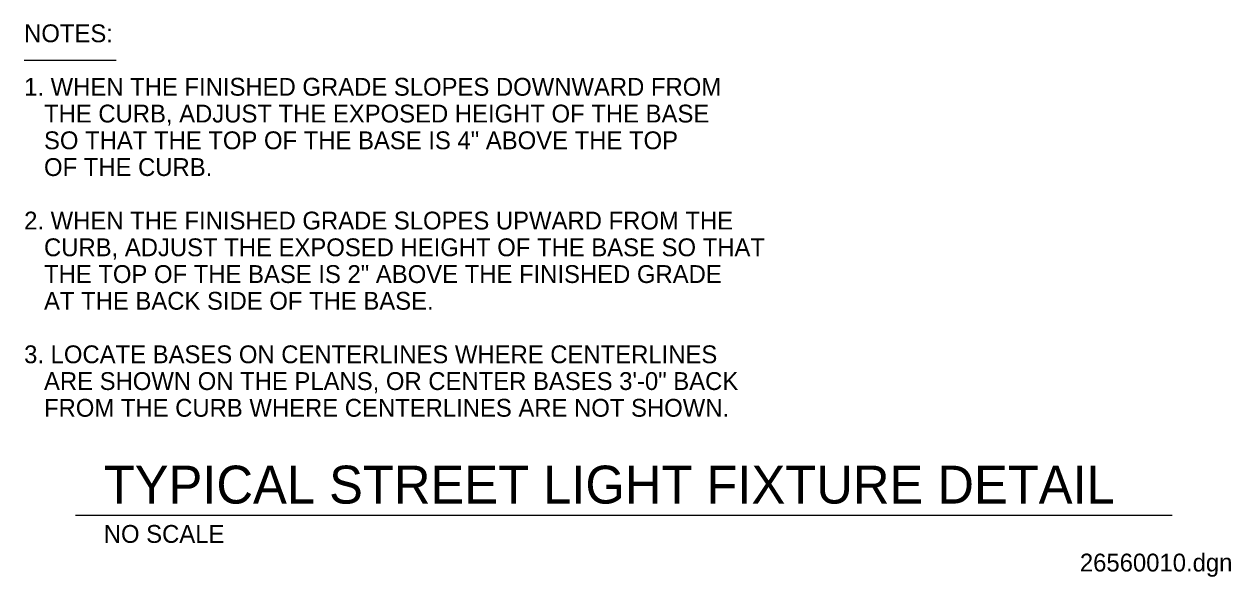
# Model space of a CAD drawing. Extents: x 10112 to 10168, y 10050 to 10179.
# Drawn here: x 10119.91 to 10165.01, y 10050.13 to 10070.8 of the extents above; entities that cross this region are included whole.
import ezdxf

# ---------------------------------------------------------------- set-up
doc = ezdxf.new("R2010")
doc.units = 0
doc.layers.add('G-ANNO-TEXT', color=7, linetype='Continuous')

msp = doc.modelspace()

# ---------------------------------------------------------------- linework, layer by layer
at = {"layer": 'G-ANNO-TEXT'}
for p, q in [((10119.906, 10069.453), (10123.34, 10069.453)), ((10121.82, 10052.441), (10162.811, 10052.441))]:
    msp.add_line(p, q, dxfattribs=at)

# ---------------------------------------------------------------- texts
for s, height, p in [('NOTES:', 0.6667, (10119.906, 10070.12)), ('1. WHEN THE FINISHED GRADE SLOPES DOWNWARD FROM', 0.66667, (10119.906, 10068.12)), ('   THE CURB, ADJUST THE EXPOSED HEIGHT OF THE BASE ', 0.66667, (10119.906, 10067.12)), ('   SO THAT THE TOP OF THE BASE IS 4" ABOVE THE TOP ', 0.66667, (10119.906, 10066.12)), ('   OF THE CURB.', 0.66667, (10119.906, 10065.12)), ('2. WHEN THE FINISHED GRADE SLOPES UPWARD FROM THE ', 0.66667, (10119.906, 10063.12)), ('   CURB, ADJUST THE EXPOSED HEIGHT OF THE BASE SO THAT ', 0.66667, (10119.906, 10062.12)), ('   THE TOP OF THE BASE IS 2" ABOVE THE FINISHED GRADE ', 0.66667, (10119.906, 10061.12)), ('   AT THE BACK SIDE OF THE BASE.', 0.66667, (10119.906, 10060.12)), ('3. LOCATE BASES ON CENTERLINES WHERE CENTERLINES', 0.66667, (10119.906, 10058.12)), ('   ARE SHOWN ON THE PLANS, OR CENTER BASES 3\'-0" BACK ', 0.66667, (10119.906, 10057.12)), ('   FROM THE CURB WHERE CENTERLINES ARE NOT SHOWN.', 0.66667, (10119.906, 10056.12)), ('TYPICAL STREET LIGHT FIXTURE DETAIL', 1.41667, (10122.883, 10052.874)), ('NO SCALE', 0.6667, (10122.883, 10051.406)), ('26560010.dgn', 0.66667, (10159.367, 10050.335))]:
    msp.add_text(s, height=height, dxfattribs=at).set_placement(p)

doc.saveas('drawing.dxf')
